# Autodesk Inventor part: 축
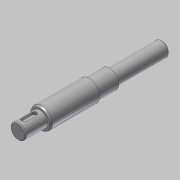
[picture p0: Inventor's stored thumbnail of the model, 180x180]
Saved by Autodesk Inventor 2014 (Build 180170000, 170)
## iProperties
Created: 2019-01
Part Number: 축
Material: 강철, 탄소
Document SubType Name: Modeling
Designer: mduedu
Density: 7.87 g/cm^3
Mass: 452.778 g
Surface Area: 120.904 cm^2
Volume: 57.5322 cm^3
Appearance: 강철
Author: mduedu
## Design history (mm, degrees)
sketch "스케치1"
  geometry: L1 (0, 0)-(26, 0); L2 (26, 0)-(26, 9); L3 (26, 9)-(0, 9); L4 (0, 9)-(0, 0); L5 (26, 0)-(84, 0); L6 (84, 0)-(84, 12.5); L7 (84, 12.5)-(26, 12.5); L8 (26, 12.5)-(26, 0); L9 (84, 0)-(108, 0); L10 (108, 0)-(108, 11); L11 (108, 11)-(84, 11); L12 (84, 11)-(84, 0); L13 (108, 0)-(170, 0); L14 (170, 0)-(170, 8.5); L15 (170, 8.5)-(108, 8.5); L16 (108, 8.5)-(108, 0)
  constraints: 32 end point, 8 parallel, 4 horizontal, 4 perpendicular
  dimensions: "d0" = 170 distance between parallel lines of L14 L4; "d2" = 26 distance of L2.end L3.end; "d3" = 24 distance of L10.end L11.end; "d4" = 62 distance of L14.end L15.end; "d5" = 18 diameter of L3 L1; "d6" = 25 diameter of L7 L5; "d7" = 22 diameter of L11 L9; "d8" = 17 diameter of L15 L13
revolve "회전1" sketch "스케치1" stored, may be unused: angle "d9" = 90 deg
node "작업 평면1"
sketch "스케치2" dims "d13" = 18
  geometry: L1 (6, -3)-(-6, -3); L2 (-6, -3)-(-6, 3); L3 (-6, 3)-(6, 3); L4 (6, 3)-(6, -3); L5 (13, 9)-(13, -9) reference; 3 further points
  constraints: 8 end point, 2 midpoint, 2 parallel, 2 vertical alignment, 1 horizontal, 1 horizontal alignment, 1 perpendicular, 4 other
  dimensions: "d10" = 6 distance between parallel lines of L3 L1; "d12" = 4 dimension on L5
extrude "돌출1" cut sketch "스케치2" distance "d14" = 3.5; taper "d15" = 0 deg
node "작업 평면2"
sketch "스케치3" dims "d19" = 20
  geometry: L1 (-21.5, -2.5)-(-6.5, -2.5); L2 (-6.5, -2.5)-(-6.5, 2.5); L3 (-6.5, 2.5)-(-21.5, 2.5); L4 (-21.5, 2.5)-(-21.5, -2.5); L5 (-31, 8.5)-(-31, -8.5) reference; 3 further points
  constraints: 8 end point, 2 midpoint, 2 parallel, 2 vertical alignment, 1 horizontal, 1 horizontal alignment, 1 perpendicular, 4 other
  dimensions: "d16" = 5 distance between parallel lines of L3 L1; "d18" = 7 dimension on L5
extrude "돌출2" cut sketch "스케치3" distance "d20" = 3; taper "d21" = 0 deg
chamfer "모따기1" distance "d22" = 1; stored, may be unused: second distance "d23" = 2, angle "d24" = 45 deg
chamfer "모따기2" distance "d25" = 2; stored, may be unused: second distance "d26" = 2, angle "d27" = 30 deg
fillet "모깎기2" dims "d30" = 2
node "솔리드1"
